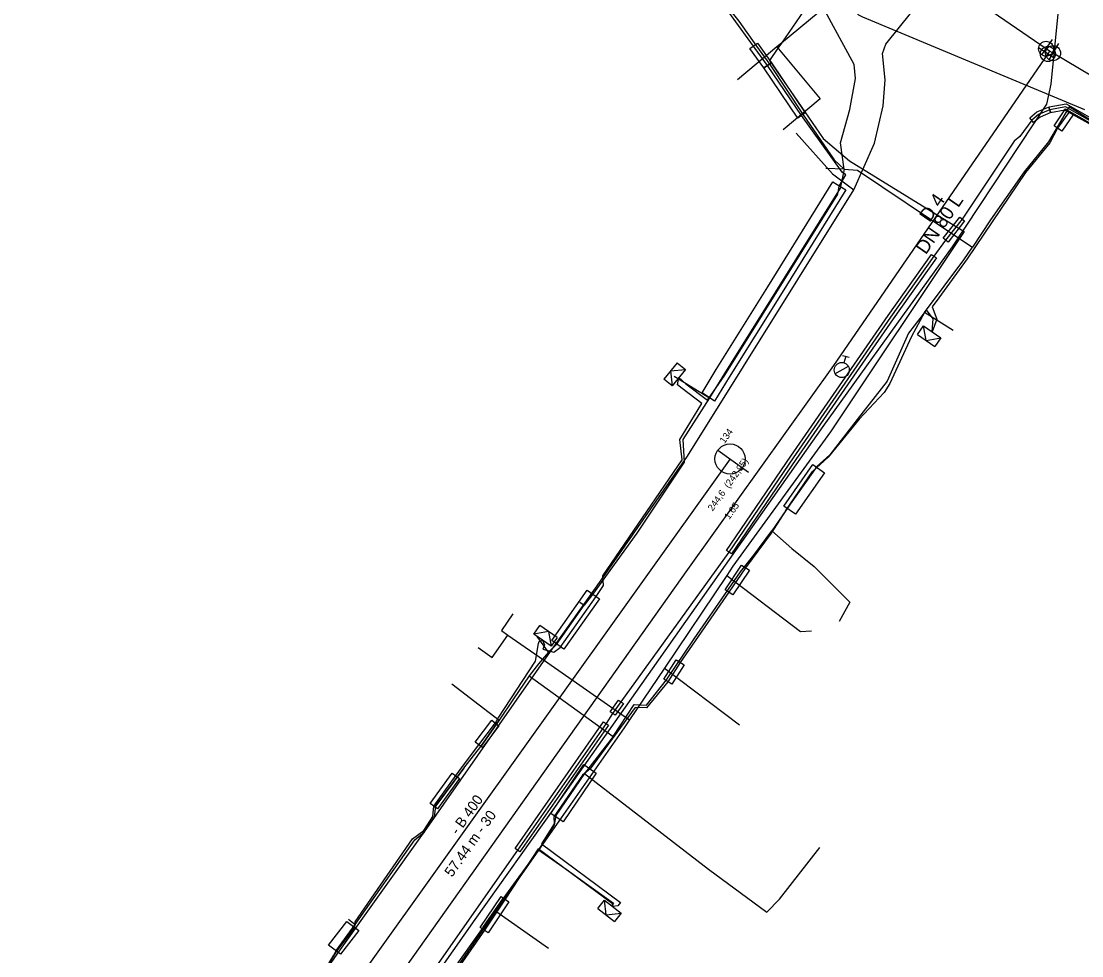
# Model space of a CAD drawing. Extents: x -600636 to -600148, y -1203980 to -1203569.
# Drawn here: x -600384.3 to -600313.9, y -1203740.1 to -1203678.1 of the extents above; entities that cross this region are included whole.
import ezdxf

# ---------------------------------------------------------------- set-up
doc = ezdxf.new("R2010")
doc.units = 0
for name, color, linetype in [('Cetin zam průběh', 7, 'Continuous'), ('EON podzemní NN', 7, 'Continuous'), ('EON podzemní VN', 7, 'Continuous'), ('GasNet NTL', 7, 'Continuous'), ('Implicitní', 7, 'Continuous'), ('VaK Břeclav_kanalizace', 7, 'Continuous'), ('VaK Břeclav_kanalizace_popis', 7, 'Continuous'), ('Vak Břeclav_vodovod', 7, 'Continuous'), ('Vak Břeclav_vodovod_popis', 7, 'Continuous'), ('Vrstva 9', 7, 'Continuous')]:
    doc.layers.add(name, color=color, linetype=linetype)

# ---------------------------------------------------------------- blocks, each defined once
blk = doc.blocks.new('NN630')
at = {"layer": 'Vrstva 9'}
for points in [[(-0.003, -0.7), (-0.703, 0)], [(-0.703, -0.7), (-0.703, 0), (0.697, 0), (0.697, -0.7)], [(-0.703, -0.7), (0.697, -0.7)], [(-0.003, -0.7), (0.697, 0)]]:
    blk.add_lwpolyline(points, dxfattribs=at)
blk = doc.blocks.new('MoSymbol 2')
at = {"layer": 'Implicitní'}
blk.add_line((0, 0.0005), (0, -0.00075), dxfattribs=at)
blk.add_circle((0, 0), 0.0005, dxfattribs=at)
blk = doc.blocks.new('MoSymbol 3')
at = {"layer": 'Implicitní'}
for p, q in [((-0.000225, 0.00095), (0.000225, 0.00095)), ((0, 0.00095), (0, 0.0005)), ((-0.000365, -0.000365), (0.000365, 0.000365))]:
    blk.add_line(p, q, dxfattribs=at)
blk.add_circle((0, 0), 0.0005, dxfattribs=at)

msp = doc.modelspace()

# ---------------------------------------------------------------- linework, layer by layer
at = {"layer": 'Cetin zam průběh'}
for points in [[(-600329.02, -1203689.27), (-600327.65, -1203686.16), (-600327.07, -1203683.69), (-600326.94, -1203681.95), (-600327.13, -1203680.22), (-600326.9, -1203679.6), (-600320.9, -1203672.11), (-600319.87, -1203671.25), (-600312.14, -1203676.45), (-600307.68, -1203679.27), (-600299.7, -1203684.11), (-600292.77, -1203688.32), (-600284.45, -1203693.32), (-600273.46, -1203699.98), (-600262.73, -1203706.4), (-600257.97, -1203709.2), (-600243.31, -1203717.93), (-600240.56, -1203720.13), (-600238.73, -1203718.32)], [(-600341.99, -1203672.1), (-600339.02, -1203675.1), (-600336.67, -1203678.06), (-600335.49, -1203679.73), (-600334.6, -1203680.94), (-600332.38, -1203684.29), (-600330.34, -1203687.27), (-600329.66, -1203687.89)], [(-600329.66, -1203687.89), (-600329.92, -1203686.15), (-600329.28, -1203683.93), (-600328.92, -1203681.87), (-600329, -1203680.95), (-600330.94, -1203677.41), (-600331.52, -1203676.9)], [(-600335.49, -1203679.73), (-600334.6, -1203680.94)], [(-600334.6, -1203680.94), (-600332.38, -1203684.29)], [(-600291.91, -1203697.34), (-600294.89, -1203695.51), (-600296.18, -1203694.98), (-600299.85, -1203692.83), (-600301.61, -1203691.58), (-600303.13, -1203690.66), (-600304.86, -1203689.65), (-600306.01, -1203688.96), (-600312.14, -1203685.36), (-600314.73, -1203683.76), (-600316.09, -1203686.08)], [(-600332.86, -1203685.5), (-600330.45, -1203688.2), (-600329.02, -1203689.27)], [(-600316.09, -1203686.08), (-600317.72, -1203688.07), (-600319.94, -1203691.26), (-600321.15, -1203693.08)], [(-600329.66, -1203687.89), (-600329.93, -1203689.16), (-600334.23, -1203696.05), (-600337.61, -1203701.47), (-600338.62, -1203703.09)], [(-600329.66, -1203687.89), (-600330.88, -1203687.85)], [(-600329.66, -1203687.89), (-600328.78, -1203687.96), (-600322.25, -1203692.35), (-600321.15, -1203693.08)], [(-600328.78, -1203687.96), (-600322.25, -1203692.35)], [(-600448.32, -1203764.77), (-600445.41, -1203766.9), (-600434.97, -1203774.92), (-600422.32, -1203783.12), (-600413.93, -1203789.04), (-600405.18, -1203794.93), (-600400.25, -1203797.98), (-600398.96, -1203798.36), (-600397.12, -1203797.36), (-600388.96, -1203781.95), (-600378.33, -1203762.13), (-600375.93, -1203758.23), (-600373.1, -1203754.01), (-600370.24, -1203749.96), (-600363.35, -1203740.04), (-600357.38, -1203731.69), (-600349.33, -1203720.15), (-600345.8, -1203715.19), (-600340.07, -1203706.96), (-600329.02, -1203689.27)], [(-600329.93, -1203689.16), (-600334.23, -1203696.05)], [(-600324.32, -1203697.42), (-600321.71, -1203693.92), (-600321.15, -1203693.08)], [(-600324.32, -1203697.42), (-600325.2, -1203699.01), (-600326.63, -1203702.13)], [(-600322.43, -1203698.61), (-600324.32, -1203697.42)], [(-600340.96, -1203701.64), (-600338.62, -1203703.09)], [(-600337.61, -1203701.47), (-600338.62, -1203703.09)], [(-600326.63, -1203702.13), (-600327, -1203702.72), (-600328.66, -1203704.49), (-600330.72, -1203707.02), (-600331.77, -1203707.97), (-600333.55, -1203710.56), (-600334.48, -1203711.92)], [(-600338.62, -1203703.09), (-600340.39, -1203705.86), (-600340.29, -1203707.36), (-600343.45, -1203712.08), (-600346.39, -1203716.15), (-600346.93, -1203716.85)], [(-600333.55, -1203710.56), (-600331.77, -1203707.97)], [(-600345.02, -1203725.57), (-600343.61, -1203723.45), (-600342.8, -1203723.5), (-600341.47, -1203721.81), (-600339.64, -1203719.08), (-600336.56, -1203714.64), (-600335.67, -1203713.53), (-600334.48, -1203711.92)], [(-600334.48, -1203711.92), (-600333.14, -1203713.1), (-600331.65, -1203714.28), (-600329.3, -1203716.65), (-600330, -1203717.93)], [(-600348.77, -1203719.46), (-600346.93, -1203716.85), (-600346.39, -1203716.15)], [(-600347.22, -1203716.65), (-600346.93, -1203716.85)], [(-600349.3, -1203719.98), (-600348.77, -1203719.46), (-600346.93, -1203716.85)], [(-600349.3, -1203719.98), (-600350.05, -1203718.94)], [(-600349.3, -1203719.98), (-600349.98, -1203720.75), (-600350.59, -1203721.54)], [(-600350.59, -1203721.54), (-600351.64, -1203723.07)], [(-600350.59, -1203721.54), (-600345.02, -1203725.57)], [(-600355.72, -1203722.09), (-600353.92, -1203723.48), (-600352.59, -1203724.49)], [(-600351.64, -1203723.07), (-600352.59, -1203724.49)], [(-600362.14, -1203738.07), (-600358.19, -1203732.44), (-600357.54, -1203731.91), (-600356.89, -1203730.92), (-600356.8, -1203730.18), (-600354.93, -1203727.69), (-600353.8, -1203726.24), (-600352.59, -1203724.49)], [(-600352.59, -1203724.49), (-600353.8, -1203726.24)], [(-600345.02, -1203725.57), (-600346.92, -1203728.04)], [(-600354.93, -1203727.69), (-600356.8, -1203730.18)], [(-600346.92, -1203728.04), (-600348.83, -1203730.83), (-600348.92, -1203731.44), (-600349.98, -1203733.11)], [(-600348.83, -1203730.83), (-600346.92, -1203728.04)], [(-600346.92, -1203728.04), (-600338.68, -1203734.38), (-600334.81, -1203737.25), (-600333.97, -1203736.39), (-600331.29, -1203732.95)], [(-600349.98, -1203733.11), (-600352.35, -1203736.35), (-600353.65, -1203738.25), (-600357.31, -1203743.38), (-600359.31, -1203746.17), (-600359.98, -1203746.53), (-600361.18, -1203748.34)], [(-600349.98, -1203733.11), (-600348.14, -1203734.39), (-600346.78, -1203735.36), (-600344.99, -1203736.64), (-600345.13, -1203736.85)], [(-600353.65, -1203738.25), (-600352.35, -1203736.35)], [(-600362.59, -1203737.71), (-600362.14, -1203738.07)], [(-600371.33, -1203751.67), (-600367.69, -1203746.37), (-600365.25, -1203742.89), (-600363.56, -1203740.1), (-600363.39, -1203739.78), (-600362.14, -1203738.07)], [(-600362.14, -1203738.07), (-600363.39, -1203739.78)], [(-600365.25, -1203742.89), (-600363.56, -1203740.1)]]:
    msp.add_lwpolyline(points, dxfattribs=at)
at = {"layer": 'EON podzemní NN'}
for points in [[(-600364.409, -1203741.504), (-600363.365, -1203739.833), (-600362.171, -1203738.261), (-600362.154, -1203737.878), (-600358.34, -1203732.37), (-600357.58, -1203731.83), (-600356.98, -1203730.9), (-600356.92, -1203730.2), (-600355.15, -1203727.74), (-600353.93, -1203726.13), (-600352.83, -1203724.67), (-600352.64, -1203724.36), (-600350.16, -1203720.58), (-600349.974, -1203719.405), (-600349.918, -1203719.261), (-600349.71, -1203719.17), (-600349.578, -1203719.49), (-600349.688, -1203719.771), (-600348.944, -1203719.986), (-600348.538, -1203719.669), (-600346.141, -1203716.287), (-600345.646, -1203715.55), (-600345.687, -1203714.9), (-600340.43, -1203707.19), (-600340.58, -1203705.85), (-600339.125, -1203703.456), (-600340.432, -1203702.472), (-600340.728, -1203702.213), (-600340.66, -1203701.74), (-600340.18, -1203702.162), (-600338.756, -1203703.234), (-600337.583, -1203701.581), (-600330.091, -1203689.555), (-600330, -1203689.03), (-600329.55, -1203688.27), (-600329.79, -1203688.1), (-600332.51, -1203684.34), (-600334.77, -1203681), (-600337.32, -1203677.47)], [(-600300.1, -1203693.14), (-600300.09, -1203692.82), (-600302.356, -1203691.251), (-600303.624, -1203690.511), (-600305.35, -1203689.5), (-600311.54, -1203685.86), (-600314.7, -1203684.06), (-600315.49, -1203685.17), (-600316.007, -1203686.155), (-600317.63, -1203688.11), (-600321.5, -1203693.84), (-600323.385, -1203696.438)], [(-600323.385, -1203696.438), (-600323.817, -1203697.034), (-600323.521, -1203697.85), (-600323.824, -1203698.698), (-600323.753, -1203697.835), (-600324.207, -1203697.234), (-600325.017, -1203698.307)], [(-600325.017, -1203698.307), (-600325.386, -1203698.796), (-600326.82, -1203701.97), (-600328.814, -1203704.512), (-600330.617, -1203706.864), (-600331.49, -1203707.646), (-600333.526, -1203710.518), (-600334.519, -1203712.072), (-600336.22, -1203714.37), (-600337.32, -1203716), (-600340.56, -1203720.66), (-600341.38, -1203721.95), (-600342.79, -1203723.669), (-600343.55, -1203723.65), (-600346.55, -1203727.73), (-600347.052, -1203728.137), (-600348.942, -1203730.911), (-600348.932, -1203731.374), (-600349.779, -1203732.697), (-600344.525, -1203736.593), (-600344.695, -1203736.832), (-600345.04, -1203736.88), (-600345.051, -1203736.7), (-600349.996, -1203733.034), (-600352.18, -1203736.39), (-600353.56, -1203738.45), (-600357.2, -1203743.67)]]:
    msp.add_lwpolyline(points, dxfattribs=at)
for points in [[(-600335.925, -1203679.884), (-600335.429, -1203679.529), (-600334.505, -1203680.82), (-600335.011, -1203681.161)], [(-600335.011, -1203681.161), (-600334.505, -1203680.82), (-600332.249, -1203684.162), (-600332.754, -1203684.503)], [(-600314.955, -1203683.887), (-600314.443, -1203684.24), (-600315.216, -1203685.361), (-600315.728, -1203685.008)], [(-600330.418, -1203688.745), (-600329.562, -1203689.263), (-600333.895, -1203696.258), (-600337.308, -1203701.715), (-600338.28, -1203703.313), (-600339.108, -1203702.752), (-600338.16, -1203701.191), (-600334.737, -1203695.718)], [(-600331.743, -1203707.518), (-600330.967, -1203708.065), (-600332.905, -1203710.817), (-600333.681, -1203710.271)], [(-600336.476, -1203714.193), (-600335.962, -1203714.539), (-600337.061, -1203716.17), (-600337.571, -1203715.829)], [(-600346.738, -1203715.862), (-600345.921, -1203716.438), (-600348.279, -1203719.778), (-600349.094, -1203719.203)], [(-600340.822, -1203720.482), (-600340.299, -1203720.816), (-600341.122, -1203722.104), (-600341.641, -1203721.775)], [(-600353.075, -1203724.495), (-600352.596, -1203724.858), (-600353.693, -1203726.306), (-600354.171, -1203725.944)], [(-600355.717, -1203728.014), (-600355.226, -1203728.369), (-600356.679, -1203730.377), (-600357.17, -1203730.022)], [(-600346.964, -1203727.443), (-600346.136, -1203728.005), (-600348.334, -1203731.245), (-600349.154, -1203730.692)], [(-600352.459, -1203736.202), (-600351.936, -1203736.553), (-600353.317, -1203738.612), (-600353.836, -1203738.265)], [(-600362.708, -1203737.856), (-600361.914, -1203738.463), (-600363.116, -1203740.036), (-600363.911, -1203739.429)]]:
    msp.add_lwpolyline(points, close=True, dxfattribs=at)
at = {"layer": 'EON podzemní VN'}
for points in [[(-600366.95, -1203635.593), (-600366.181, -1203636.795), (-600358.381, -1203643.411), (-600344.954, -1203653.759), (-600330.827, -1203664.425), (-600321.645, -1203670.963), (-600317.713, -1203673.458), (-600315.791, -1203674.896), (-600315.293, -1203675.777), (-600315.944, -1203682.246), (-600316.226, -1203683.581), (-600322.501, -1203693.042), (-600331.079, -1203704.985), (-600348.911, -1203730.288), (-600354.208, -1203737.743), (-600361.516, -1203748.136), (-600365.138, -1203753.003), (-600368.824, -1203758.254), (-600375.091, -1203769.039), (-600381.398, -1203780.278), (-600382.49, -1203782.6), (-600383.25, -1203783.59)], [(-600313.007, -1203684.869), (-600314.967, -1203683.759), (-600316.007, -1203683.949), (-600316.757, -1203684.269), (-600317.207, -1203684.639), (-600317.997, -1203685.729), (-600318.367, -1203686.039), (-600321.837, -1203691.209), (-600322.927, -1203692.609), (-600323.707, -1203693.669), (-600326.587, -1203697.729), (-600333.047, -1203707.069), (-600337.327, -1203713.329), (-600344.497, -1203723.269), (-600345.047, -1203724.049), (-600345.487, -1203724.709), (-600351.367, -1203733.129), (-600357.517, -1203741.909)]]:
    msp.add_lwpolyline(points, dxfattribs=at)
for points in [[(-600313.105, -1203685.043), (-600315.002, -1203683.969), (-600315.971, -1203684.146), (-600316.043, -1203683.752), (-600314.931, -1203683.549), (-600312.908, -1203684.695)], [(-600316.085, -1203683.765), (-600315.928, -1203684.133), (-600316.652, -1203684.442), (-600317.08, -1203684.793), (-600317.334, -1203684.484), (-600316.861, -1203684.096)], [(-600321.994, -1203691.086), (-600321.679, -1203691.332), (-600322.769, -1203692.732), (-600323.084, -1203692.486)], [(-600323.87, -1203693.553), (-600323.543, -1203693.785), (-600326.423, -1203697.844), (-600332.882, -1203707.182), (-600337.162, -1203713.442), (-600337.492, -1203713.216), (-600333.211, -1203706.956), (-600326.75, -1203697.614)], [(-600344.66, -1203723.154), (-600344.333, -1203723.384), (-600344.883, -1203724.164), (-600345.21, -1203723.934)], [(-600345.651, -1203724.594), (-600345.323, -1203724.823), (-600351.203, -1203733.243), (-600351.531, -1203733.014)]]:
    msp.add_lwpolyline(points, close=True, dxfattribs=at)
at = {"layer": 'GasNet NTL'}
for points in [[(-600309.24, -1203678.67), (-600322.08, -1203669.74), (-600324.1, -1203669.99), (-600324.38, -1203670.02), (-600324.57, -1203670.3), (-600329.11, -1203676.87), (-600329.27, -1203677.14), (-600328.72, -1203677.64), (-600328.46, -1203677.78), (-600313.71, -1203683.92)], [(-600331.63, -1203676.31), (-600333.84, -1203679.52), (-600334.07, -1203679.86), (-600334.63, -1203680.67), (-600332.29, -1203684.08), (-600331.07, -1203685.85), (-600329.31, -1203687.34), (-600321.69, -1203692.03)], [(-600330.12, -1203676.43), (-600333.84, -1203679.52), (-600334.14, -1203679.77)], [(-600334.14, -1203679.77), (-600336.75, -1203681.95)], [(-600334.14, -1203679.77), (-600331.26, -1203683.23), (-600333.72, -1203685.28)], [(-600321.69, -1203692.03), (-600330.58, -1203705.33), (-600337.06, -1203714.26), (-600337.47, -1203714.88), (-600341.61, -1203721.03), (-600343.93, -1203724.48), (-600344.29, -1203725.01), (-600352.8, -1203737.19), (-600355.42, -1203740.94), (-600356.36, -1203742.04), (-600356.56, -1203742.28), (-600357.37, -1203743.06), (-600358.82, -1203744.14), (-600359.04, -1203744.31), (-600359.16, -1203744.4), (-600365.08, -1203752.77), (-600365.18, -1203752.95), (-600368.57, -1203759.1), (-600375.05, -1203770.85), (-600375.18, -1203771.08)], [(-600337.47, -1203714.88), (-600332.57, -1203718.61), (-600331.83, -1203718.55)], [(-600351.67, -1203717.44), (-600352.44, -1203718.54), (-600352.01, -1203718.84)], [(-600353.98, -1203719.66), (-600353.04, -1203720.32), (-600352.01, -1203718.84)], [(-600352.01, -1203718.84), (-600349.36, -1203720.69), (-600344.44, -1203724.12), (-600343.93, -1203724.48)], [(-600341.61, -1203721.03), (-600336.63, -1203724.81)], [(-600352.8, -1203737.19), (-600349.31, -1203739.63)]]:
    msp.add_lwpolyline(points, dxfattribs=at)
at = {"layer": 'VaK Břeclav_kanalizace'}
msp.add_line((-600337.248, -1203707.145), (-600370.65, -1203753.88), dxfattribs=at)
at = {"layer": 'Vak Břeclav_vodovod'}
for p, q in [((-600316.022, -1203680.054), (-600316.256, -1203679.894)), ((-600316.022, -1203680.054), (-600316.133, -1203680.243)), ((-600315.791, -1203680.191), (-600316.022, -1203680.054)), ((-600316.133, -1203680.243), (-600330.382, -1203700.926))]:
    msp.add_line(p, q, dxfattribs=at)
for points in [[(-600316.256, -1203679.894), (-600332.434, -1203668.792), (-600354.837, -1203651.734), (-600377.846, -1203634.299)], [(-600236.89, -1203728.365), (-600242.377, -1203724.953), (-600264, -1203711.729), (-600288.949, -1203696.473), (-600297.916, -1203690.812), (-600315.791, -1203680.191)], [(-600330.382, -1203700.926), (-600340.064, -1203714.494), (-600360.044, -1203742.638), (-600371.815, -1203758.94), (-600385.686, -1203786.009), (-600395.742, -1203804.116)]]:
    msp.add_lwpolyline(points, dxfattribs=at)

# ---------------------------------------------------------------- block references
at = {"layer": 'EON podzemní NN'}
for p, rotation in [((-600323.824, -1203698.698), -34.76214450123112), ((-600340.66, -1203701.74), -129.16428899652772), ((-600349.71, -1203719.17), 144.98242772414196), ((-600345.04, -1203736.88), -37.60859440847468)]:
    msp.add_blockref('NN630', p, dxfattribs=dict(at, rotation=rotation))
at = {"layer": 'VaK Břeclav_kanalizace', "xscale": 1999.750031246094, "yscale": 1999.7500312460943, "rotation": 54.44620557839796}
msp.add_blockref('MoSymbol 2', (-600337.248, -1203707.145), dxfattribs=at)
at = {"layer": 'Vak Břeclav_vodovod', "yscale": 999.8750156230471}
for name, p, xscale, rotation in [('MoSymbol 2', (-600316.133, -1203680.243), 999.875015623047, -122.49482217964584), ('MoSymbol 2', (-600316.256, -1203679.894), 999.8750156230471, 145.54188289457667), ('MoSymbol 2', (-600315.791, -1203680.191), 999.8750156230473, 149.2825871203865), ('MoSymbol 3', (-600329.824, -1203701.236), 999.8750156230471, -16.440379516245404)]:
    msp.add_blockref(name, p, dxfattribs=dict(at, xscale=xscale, rotation=rotation))

# ---------------------------------------------------------------- texts
at = {"layer": 'VaK Břeclav_kanalizace_popis'}
for s, height, p in [('134', 0.4549, (-600337.613, -1203706.156)), ('244,6  (242,95)', 0.45494, (-600338.402, -1203710.642)), ('1.65', 0.4549, (-600337.3, -1203711.2)), ('- B 400', 0.6824, (-600355.328, -1203732.16)), ('57.44 m - 30', 0.68241, (-600355.718, -1203734.961))]:
    msp.add_text(s, height=height, rotation=54.44621, dxfattribs=at).set_placement(p)
at = {"layer": 'Vak Břeclav_vodovod_popis'}
for s, p in [('DN 80 L', (-600324.241, -1203693.616)), ('D 4', (-600323.995, -1203691.479))]:
    msp.add_text(s, height=0.9099, rotation=55.43614, dxfattribs=at).set_placement(p)

doc.saveas('drawing.dxf')
